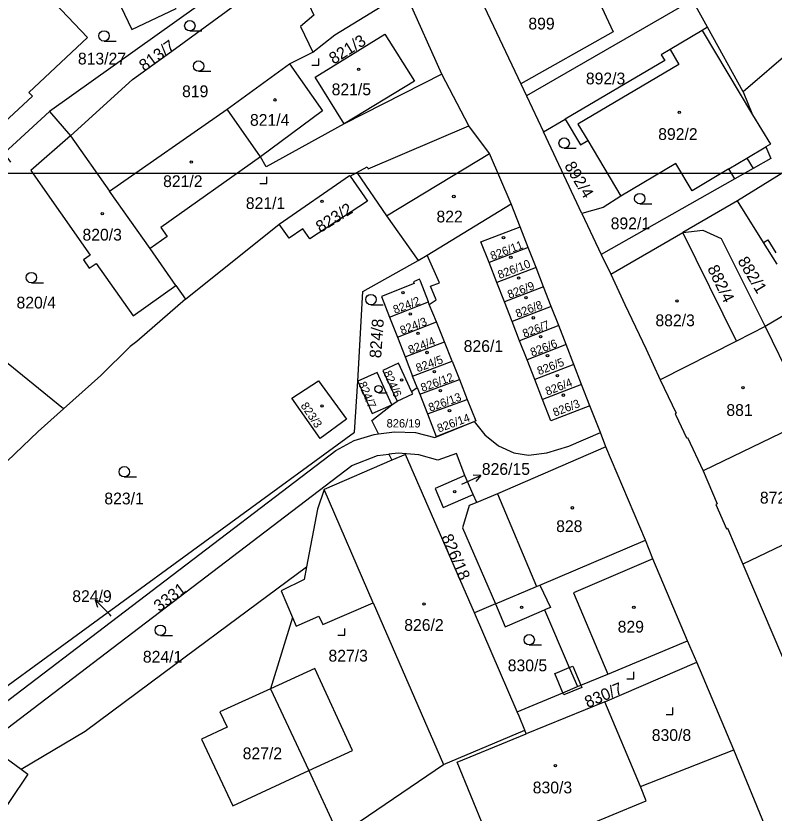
# Model space of a CAD drawing. Extents: x -496682 to -495776, y -1088797 to -1088018.
# Drawn here: x -496303.3 to -496193.9, y -1088256.7 to -1088141.5 of the extents above; entities that cross this region are included whole.
import ezdxf

# ---------------------------------------------------------------- set-up
doc = ezdxf.new("R2010")
doc.units = 0
for name, color, linetype in [('Hranice parcel', 7, 'Continuous'), ('Parcelní čísla', 7, 'Continuous'), ('Pop  PČ popisy', 7, 'Continuous'), ('Vnitřní kresba', 7, 'Continuous'), ('Vrstva 63', 7, 'Continuous'), ('Značky budov', 7, 'Continuous'), ('Značky kultur', 7, 'Continuous')]:
    doc.layers.add(name, color=color, linetype=linetype)

msp = doc.modelspace()

# ---------------------------------------------------------------- linework, layer by layer
at = {"layer": 'Hranice parcel'}
for p, q in [((-496241.8, -1088149.94), (-496247.14, -1088138.02)), ((-496205.62, -1088139.25), (-496229.59, -1088153.09)), ((-496203.46, -1088143.17), (-496205.62, -1088139.25)), ((-496198.32, -1088152.5), (-496203.46, -1088143.17)), ((-496187.08, -1088142.78), (-496198.32, -1088152.5)), ((-496263.79, -1088148.47), (-496260.45, -1088146.79)), ((-496272.8, -1088155.01), (-496263.79, -1088148.47)), ((-496237.95, -1088157.41), (-496241.8, -1088149.94)), ((-496229.59, -1088153.09), (-496227.14, -1088158.28)), ((-496298.45, -1088155.33), (-496295.42, -1088158.88)), ((-496289.8, -1088166.88), (-496272.8, -1088155.01)), ((-496268.02, -1088161.9), (-496272.8, -1088155.01)), ((-496227.14, -1088158.28), (-496224.02, -1088156.48)), ((-496295.42, -1088158.88), (-496289.8, -1088166.88)), ((-496221.59, -1088170.07), (-496227.14, -1088158.28)), ((-496255.04, -1088164.71), (-496254.07, -1088164.17)), ((-496199.54, -1088165.08), (-496218.8, -1088175.99)), ((-496283.92, -1088175.15), (-496289.8, -1088166.88)), ((-496199.12, -1088168.24), (-496207.04, -1088172.83)), ((-496243.96, -1088176.09), (-496231.8, -1088168.7)), ((-496230.52, -1088171.99), (-496231.8, -1088168.7)), ((-496221.59, -1088170.07), (-496218.8, -1088175.99)), ((-496278.83, -1088182.48), (-496265.29, -1088171.61)), ((-496229.35, -1088174.98), (-496230.52, -1088171.99)), ((-496217.42, -1088178.85), (-496207.04, -1088172.83)), ((-496199.29, -1088188.52), (-496207.04, -1088172.83)), ((-496280.24, -1088180.51), (-496283.92, -1088175.15)), ((-496229.35, -1088174.98), (-496234.99, -1088177.17)), ((-496228.23, -1088177.87), (-496229.35, -1088174.98)), ((-496245.26, -1088176.88), (-496243.96, -1088176.09)), ((-496218.8, -1088175.99), (-496217.42, -1088178.85)), ((-496233.87, -1088180.06), (-496234.99, -1088177.17)), ((-496228.23, -1088177.87), (-496233.87, -1088180.06)), ((-496227.14, -1088180.67), (-496228.23, -1088177.87)), ((-496296.45, -1088198.31), (-496318.2, -1088180.61)), ((-496280.24, -1088180.51), (-496278.83, -1088182.48)), ((-496232.78, -1088182.86), (-496233.87, -1088180.06)), ((-496227.14, -1088180.67), (-496232.78, -1088182.86)), ((-496226.03, -1088183.51), (-496227.14, -1088180.67)), ((-496249.36, -1088185.06), (-496243.73, -1088182.86)), ((-496243.63, -1088183.24), (-496243.73, -1088182.86)), ((-496242.58, -1088185.76), (-496243.63, -1088183.24)), ((-496231.67, -1088185.7), (-496232.78, -1088182.86)), ((-496226.03, -1088183.51), (-496231.67, -1088185.7)), ((-496224.95, -1088186.28), (-496226.03, -1088183.51)), ((-496190.77, -1088183.83), (-496195.13, -1088186.39)), ((-496249.36, -1088185.06), (-496248.24, -1088187.94)), ((-496248.24, -1088187.94), (-496242.58, -1088185.76)), ((-496241.45, -1088188.63), (-496242.58, -1088185.76)), ((-496230.59, -1088188.48), (-496231.67, -1088185.7)), ((-496224.95, -1088186.28), (-496230.59, -1088188.48)), ((-496223.88, -1088189.03), (-496224.95, -1088186.28)), ((-496195.13, -1088186.39), (-496199.29, -1088188.52)), ((-496248.24, -1088187.94), (-496247.13, -1088190.79)), ((-496247.13, -1088190.79), (-496241.45, -1088188.63)), ((-496240.33, -1088191.44), (-496241.45, -1088188.63)), ((-496229.52, -1088191.23), (-496230.59, -1088188.48)), ((-496223.88, -1088189.03), (-496229.52, -1088191.23)), ((-496222.77, -1088191.9), (-496223.88, -1088189.03)), ((-496199.29, -1088188.52), (-496210.3, -1088194.11)), ((-496247.13, -1088190.79), (-496246.04, -1088193.57)), ((-496246.04, -1088193.57), (-496240.33, -1088191.44)), ((-496240.33, -1088191.44), (-496239.28, -1088194.09)), ((-496228.41, -1088194.09), (-496229.52, -1088191.23)), ((-496222.77, -1088191.9), (-496228.41, -1088194.09)), ((-496221.65, -1088194.78), (-496222.77, -1088191.9)), ((-496245.4, -1088195.22), (-496246.04, -1088193.57)), ((-496245.02, -1088196.2), (-496239.28, -1088194.09)), ((-496239.28, -1088194.09), (-496238.15, -1088196.96)), ((-496227.29, -1088196.97), (-496228.41, -1088194.09)), ((-496221.65, -1088194.78), (-496227.29, -1088196.97)), ((-496220.45, -1088197.86), (-496221.65, -1088194.78)), ((-496246.18, -1088195.79), (-496245.4, -1088195.22)), ((-496245.4, -1088195.22), (-496245.02, -1088196.2)), ((-496249.06, -1088197.72), (-496248.29, -1088197.2)), ((-496245.02, -1088196.2), (-496243.91, -1088199.04)), ((-496243.91, -1088199.04), (-496238.15, -1088196.96)), ((-496218.94, -1088201.74), (-496220.45, -1088197.86)), ((-496218.13, -1088203.82), (-496218.94, -1088201.74)), ((-496212.43, -1088217.26), (-496218.13, -1088203.82)), ((-496249.48, -1088204.87), (-496249.04, -1088205.74)), ((-496237.31, -1088210.69), (-496238.5, -1088207.96)), ((-496236.79, -1088211.83), (-496237.31, -1088210.69)), ((-496198.35, -1088220.77), (-496191.24, -1088237.47)), ((-496234.09, -1088226.5), (-496237.12, -1088227.8)), ((-496230.93, -1088242.07), (-496237.12, -1088227.8)), ((-496263.4, -1088228.45), (-496266.56, -1088238.74)), ((-496205.03, -1088234.9), (-496206.35, -1088231.82)), ((-496218.27, -1088240.64), (-496205.03, -1088234.9)), ((-496199.66, -1088247.57), (-496205.03, -1088234.9)), ((-496218.27, -1088240.64), (-496229.63, -1088245.28)), ((-496213.15, -1088252.87), (-496218.27, -1088240.64)), ((-496302.57, -1088250.38), (-496293.33, -1088244.86)), ((-496241.58, -1088249.7), (-496229.85, -1088244.73)), ((-496229.63, -1088245.28), (-496229.85, -1088244.73)), ((-496307.55, -1088246.72), (-496302.57, -1088250.38)), ((-496213.15, -1088252.87), (-496199.66, -1088247.57)), ((-496188.02, -1088275.91), (-496199.66, -1088247.57)), ((-496261.03, -1088250.54), (-496256.69, -1088259.96))]:
    msp.add_line(p, q, dxfattribs=at)
for points in [[(-496284.92, -1088130.53), (-496291.31, -1088133.56), (-496286.59, -1088143.52), (-496280.17, -1088140.48), (-496284.92, -1088130.53)], [(-496265.89, -1088136.18), (-496267.72, -1088133.38), (-496298.45, -1088155.33)], [(-496262.1, -1088133.95), (-496260.32, -1088137.8), (-496261.74, -1088138.32), (-496260.3, -1088141.44), (-496262.22, -1088143.07), (-496260.45, -1088146.79)], [(-496295.42, -1088158.88), (-496286.46, -1088150.74), (-496280.26, -1088146.23), (-496271.7, -1088140.01), (-496265.89, -1088136.18)], [(-496316.44, -1088148.1), (-496316.33, -1088148), (-496315.31, -1088149.08), (-496325.51, -1088158.67), (-496317.28, -1088167.48), (-496305.43, -1088156.36), (-496304.95, -1088156.9), (-496300.93, -1088153.13), (-496301.44, -1088152.61), (-496292.98, -1088144.67), (-496299.6, -1088137.62)], [(-496260.45, -1088146.79), (-496257.27, -1088144.28), (-496247.14, -1088138.02)], [(-496236.14, -1088139.28), (-496230.41, -1088151.36), (-496229.59, -1088153.09)], [(-496203.46, -1088143.17), (-496204.25, -1088143.65), (-496208.86, -1088146.39), (-496210.14, -1088147.15), (-496209.63, -1088148), (-496224.02, -1088156.48)], [(-496250.04, -1088144.19), (-496245.79, -1088150.95), (-496255.91, -1088157.15), (-496260.09, -1088150.37), (-496250.04, -1088144.19)], [(-496263.79, -1088148.47), (-496259.06, -1088155.27), (-496268.02, -1088161.9)], [(-496241.8, -1088149.94), (-496255.91, -1088157.15), (-496267.18, -1088163.34), (-496268.02, -1088161.9)], [(-496198.32, -1088152.5), (-496196.96, -1088155.81), (-496194.39, -1088160.08), (-496195.03, -1088160.46), (-496194.34, -1088162.14), (-496196.89, -1088163.58), (-496199.54, -1088165.08)], [(-496304.04, -1088162.67), (-496305.02, -1088161.37), (-496298.45, -1088155.33)], [(-496224.02, -1088156.48), (-496221.81, -1088160.18), (-496220.77, -1088159.55), (-496215.96, -1088167.6)], [(-496254.07, -1088164.17), (-496252.59, -1088163.36), (-496252.44, -1088163.62), (-496237.95, -1088157.41)], [(-496231.8, -1088168.7), (-496234.94, -1088161.4), (-496237.95, -1088157.41)], [(-496182.92, -1088158.15), (-496186.17, -1088160.2), (-496199.12, -1088168.24)], [(-496295.42, -1088158.88), (-496301.16, -1088163.87), (-496292.58, -1088176.09), (-496293.56, -1088176.78), (-496292.71, -1088177.99), (-496291.73, -1088177.3), (-496286.4, -1088184.88), (-496280.24, -1088180.51)], [(-496268.02, -1088161.9), (-496282.4, -1088172.11), (-496281.47, -1088173.42), (-496283.92, -1088175.15)], [(-496199.54, -1088165.08), (-496200.38, -1088163.65), (-496205.67, -1088166.81), (-496208.04, -1088162.84), (-496215.96, -1088167.6)], [(-496265.29, -1088171.61), (-496255.13, -1088164.58), (-496255.04, -1088164.71)], [(-496255.04, -1088164.71), (-496252.56, -1088168.29), (-496260.9, -1088173.75), (-496261.91, -1088172.29), (-496263.88, -1088173.65), (-496265.29, -1088171.61)], [(-496254.07, -1088164.17), (-496249.82, -1088170.42), (-496245.26, -1088176.88)], [(-496215.96, -1088167.6), (-496218.53, -1088169.21), (-496221.59, -1088170.07)], [(-496193.41, -1088177.4), (-496195.37, -1088174.27), (-496199.12, -1088168.24)], [(-496234.99, -1088177.17), (-496236.17, -1088174.19), (-496230.52, -1088171.99)], [(-496207.04, -1088172.83), (-496204.16, -1088172.47), (-496201.5, -1088173.7), (-496195.13, -1088186.39)], [(-496243.63, -1088183.24), (-496242.63, -1088182.58), (-496243.44, -1088180.59), (-496242.16, -1088180.08), (-496243.96, -1088176.09)], [(-496253.97, -1088194.3), (-496253.21, -1088181.35), (-496245.26, -1088176.88)], [(-496217.42, -1088178.85), (-496215.39, -1088183.24), (-496212.35, -1088189.69), (-496210.3, -1088194.11)], [(-496243.73, -1088182.86), (-496244.92, -1088179.86), (-496245.04, -1088179.57), (-496245.9, -1088179.95), (-496245.8, -1088180.2), (-496250.53, -1088182.08), (-496249.36, -1088185.06)], [(-496278.83, -1088182.48), (-496285.87, -1088188.57), (-496286.81, -1088189.29), (-496291.03, -1088193.47), (-496296.45, -1088198.31)], [(-496246.18, -1088195.79), (-496248.08, -1088191.7), (-496250.36, -1088192.76), (-496248.29, -1088197.2)], [(-496249.06, -1088197.72), (-496251.15, -1088193.04), (-496253.97, -1088194.3)], [(-496311.81, -1088243.59), (-496254.42, -1088201.7), (-496253.97, -1088194.3)], [(-496263.48, -1088196.77), (-496259.62, -1088194.28), (-496255.59, -1088199.81)], [(-496253.97, -1088194.3), (-496251.88, -1088198.98), (-496249.06, -1088197.72)], [(-496210.3, -1088194.11), (-496208.02, -1088198.95), (-496208.16, -1088199.02), (-496208.06, -1088199.23), (-496206.51, -1088202.51), (-496206.37, -1088202.45), (-496204.1, -1088207.28)], [(-496248.29, -1088197.2), (-496246.02, -1088196.14), (-496246.18, -1088195.79)], [(-496255.59, -1088199.81), (-496259.41, -1088202.59), (-496263.48, -1088196.77)], [(-496238.15, -1088196.96), (-496236.93, -1088200.02), (-496237.18, -1088200.12)], [(-496220.45, -1088197.86), (-496226.09, -1088200.05), (-496227.29, -1088196.97)], [(-496330.37, -1088232.05), (-496329.58, -1088231.08), (-496327.35, -1088228.88), (-496319.53, -1088220.58), (-496313.61, -1088214.48), (-496300.1, -1088201.57), (-496296.45, -1088198.31)], [(-496250.98, -1088201.92), (-496251.95, -1088200), (-496249.06, -1088197.72)], [(-496185.54, -1088197.33), (-496188.66, -1088199.81), (-496204.1, -1088207.28)], [(-496243.91, -1088199.04), (-496242.64, -1088202.29), (-496237.18, -1088200.12)], [(-496250.98, -1088201.92), (-496248.64, -1088201.63), (-496245.64, -1088201.74), (-496242.85, -1088202.47), (-496237.18, -1088200.12)], [(-496237.18, -1088200.12), (-496235.63, -1088202.06), (-496233.62, -1088203.63), (-496231.44, -1088204.65), (-496229.32, -1088205), (-496226.65, -1088204.68), (-496223.49, -1088203.7), (-496218.94, -1088201.74)], [(-496310.18, -1088244.79), (-496257.12, -1088204.31), (-496254.49, -1088202.87), (-496251.61, -1088202), (-496250.98, -1088201.92)], [(-496218.13, -1088203.82), (-496233.8, -1088210.57), (-496236.79, -1088211.83)], [(-496307.55, -1088246.72), (-496254.8, -1088206.49), (-496251.12, -1088205.07), (-496249.48, -1088204.87)], [(-496238.5, -1088207.96), (-496239.73, -1088204.77), (-496242.39, -1088205.73), (-496245.16, -1088204.93), (-496248.13, -1088204.71), (-496249.48, -1088204.87)], [(-496237.12, -1088227.8), (-496247.06, -1088204.88), (-496249.04, -1088205.74)], [(-496249.04, -1088205.74), (-496258.79, -1088209.96), (-496259.78, -1088212.78), (-496261.37, -1088221.14)], [(-496204.1, -1088207.28), (-496202.07, -1088212.04), (-496202.25, -1088212.12), (-496200.73, -1088215.63), (-496200.57, -1088215.56), (-496198.35, -1088220.77)], [(-496238.5, -1088207.96), (-496242.81, -1088209.83), (-496241.65, -1088212.57), (-496237.31, -1088210.69)], [(-496236.79, -1088211.83), (-496237.87, -1088212.28), (-496238.84, -1088215.51), (-496234.09, -1088226.5)], [(-496179.86, -1088211.45), (-496182.82, -1088213.25), (-496186.02, -1088214.8), (-496198.35, -1088220.77)], [(-496234.09, -1088226.5), (-496228.16, -1088223.97), (-496227.66, -1088223.76), (-496212.43, -1088217.26)], [(-496206.35, -1088231.82), (-496211.35, -1088219.97), (-496212.43, -1088217.26)], [(-496293.33, -1088244.86), (-496282.06, -1088236.51), (-496272.7, -1088229.58), (-496261.37, -1088221.14)], [(-496261.37, -1088221.14), (-496261.72, -1088222.97), (-496265.04, -1088224.59), (-496263.4, -1088228.45)], [(-496263.4, -1088228.45), (-496262.87, -1088229.7), (-496259.56, -1088228.24), (-496259, -1088229.48), (-496251.75, -1088226.32), (-496241.58, -1088249.7)], [(-496234.09, -1088226.5), (-496232.66, -1088229.8), (-496228.12, -1088227.84), (-496227, -1088227.36), (-496223.42, -1088235.69), (-496222.24, -1088238.44)], [(-496222.24, -1088238.44), (-496221.74, -1088238.24), (-496217.87, -1088236.62), (-496206.35, -1088231.82)], [(-496261.03, -1088250.54), (-496254.74, -1088247.66), (-496260.18, -1088235.84), (-496266.56, -1088238.74)], [(-496266.56, -1088238.74), (-496273.85, -1088242.06), (-496272.81, -1088244.31), (-496276.5, -1088246.03), (-496272.01, -1088255.68), (-496261.03, -1088250.54)], [(-496230.93, -1088242.07), (-496224.34, -1088239.32), (-496222.24, -1088238.44)], [(-496229.85, -1088244.73), (-496230.66, -1088242.69), (-496230.93, -1088242.07)], [(-496233.69, -1088263.8), (-496239.59, -1088249.36), (-496229.63, -1088245.28)], [(-496256.69, -1088259.96), (-496256.02, -1088259.51), (-496241.58, -1088249.7)], [(-496302.57, -1088250.38), (-496301.59, -1088251.1), (-496306.94, -1088258.98)], [(-496233.69, -1088263.8), (-496212.34, -1088254.94), (-496213.15, -1088252.87)]]:
    msp.add_lwpolyline(points, dxfattribs=at)
at = {"layer": 'Pop  PČ popisy'}
for p, q in [((-496238.92, -1088209.2), (-496236.2, -1088207.93)), ((-496236.2, -1088207.93), (-496237.32, -1088207.9)), ((-496236.2, -1088207.93), (-496236.9, -1088208.81)), ((-496289.77, -1088228.03), (-496291.89, -1088225.91)), ((-496291.89, -1088225.91), (-496290.83, -1088226.26)), ((-496291.89, -1088225.91), (-496291.54, -1088226.97)), ((-496289.57, -1088228.24), (-496289.77, -1088228.03))]:
    msp.add_line(p, q, dxfattribs=at)
at = {"layer": 'Vnitřní kresba'}
for p, q in [((-496222.8, -1088131.48), (-496217.11, -1088143.84)), ((-496217.11, -1088143.84), (-496230.41, -1088151.36)), ((-496204.25, -1088143.65), (-496196.96, -1088155.81)), ((-496208.86, -1088146.39), (-496207.59, -1088148.55)), ((-496207.59, -1088148.55), (-496222.17, -1088157.19)), ((-496222.17, -1088157.19), (-496220.77, -1088159.55)), ((-496197.78, -1088162.1), (-496195.03, -1088160.46)), ((-496249.82, -1088170.42), (-496234.94, -1088161.4)), ((-496200.38, -1088163.65), (-496197.78, -1088162.1)), ((-496197.78, -1088162.1), (-496196.89, -1088163.58)), ((-496195.37, -1088174.27), (-496194.78, -1088173.9)), ((-496194.78, -1088173.9), (-496193.61, -1088175.79)), ((-496195.13, -1088186.39), (-496188.66, -1088199.81)), ((-496251.75, -1088226.32), (-496258.79, -1088209.96)), ((-496233.8, -1088210.57), (-496228.16, -1088223.97)), ((-496211.35, -1088219.97), (-496222.82, -1088224.87)), ((-496227.66, -1088223.76), (-496226.14, -1088226.99)), ((-496222.82, -1088224.87), (-496217.87, -1088236.62)), ((-496226.14, -1088226.99), (-496227, -1088227.36)), ((-496225.49, -1088236.52), (-496225.15, -1088236.38)), ((-496225.15, -1088236.38), (-496223.42, -1088235.69)), ((-496223.42, -1088235.69), (-496222.89, -1088235.48)), ((-496222.89, -1088235.48), (-496221.74, -1088238.24)), ((-496224.34, -1088239.32), (-496225.49, -1088236.52)), ((-496266.56, -1088238.74), (-496261.03, -1088250.54)), ((-496221.6, -1088238.57), (-496224.21, -1088239.64)), ((-496221.74, -1088238.24), (-496221.6, -1088238.57)), ((-496224.21, -1088239.64), (-496224.34, -1088239.32))]:
    msp.add_line(p, q, dxfattribs=at)
at = {"layer": 'Vrstva 63'}
msp.add_lwpolyline([(-496137.35, -1088164.24), (-496137.35, -1088461.24), (-496557.35, -1088461.24), (-496557.35, -1088164.24)], close=True, dxfattribs=at)
at = {"layer": 'Značky budov'}
for centre in [(-496253.83, -1088149.25), (-496265.91, -1088153.67), (-496207.55, -1088155.47), (-496278, -1088162.65), (-496259.11, -1088168.33), (-496240.09, -1088167.63), (-496290.84, -1088170.11), (-496232.92, -1088173.59), (-496231.86, -1088176.41), (-496230.74, -1088179.41), (-496247.44, -1088181.54), (-496229.68, -1088182.23), (-496207.89, -1088182.71), (-496246.38, -1088184.59), (-496228.62, -1088185.16), (-496245.26, -1088187.41), (-496227.57, -1088187.87), (-496243.95, -1088190.17), (-496226.57, -1088190.63), (-496242.9, -1088192.93), (-496225.14, -1088193.51), (-496247.63, -1088194.14), (-496242.03, -1088195.69), (-496224.27, -1088196.33), (-496198.35, -1088195.25), (-496259.11, -1088197.88), (-496240.72, -1088198.57), (-496239.96, -1088210.28), (-496222.97, -1088212.61), (-496244.39, -1088226.5), (-496230.3, -1088226.97), (-496214.11, -1088227), (-496225.43, -1088249.85)]:
    msp.add_circle(centre, 0.175, dxfattribs=at)
at = {"layer": 'Značky kultur'}
for p, q in [((-496278.2, -1088143.71), (-496276.45, -1088143.71)), ((-496290.59, -1088145.18), (-496288.84, -1088145.18)), ((-496259.58, -1088148.67), (-496259.58, -1088147.67)), ((-496260.58, -1088148.67), (-496259.58, -1088148.67)), ((-496276.94, -1088149.53), (-496275.19, -1088149.53)), ((-496224.16, -1088160.66), (-496222.41, -1088160.66)), ((-496267.11, -1088165.77), (-496267.11, -1088164.77)), ((-496268.11, -1088165.77), (-496267.11, -1088165.77)), ((-496213.26, -1088168.69), (-496211.51, -1088168.69)), ((-496301.08, -1088180.1), (-496299.33, -1088180.1)), ((-496252.05, -1088183.27), (-496250.3, -1088183.27)), ((-496250.96, -1088195.98), (-496249.73, -1088195.98)), ((-496287.66, -1088208.15), (-496285.91, -1088208.15)), ((-496255.82, -1088231.02), (-496255.82, -1088230.02)), ((-496282.46, -1088231.05), (-496280.71, -1088231.05)), ((-496256.82, -1088231.02), (-496255.82, -1088231.02)), ((-496229.21, -1088232.41), (-496227.46, -1088232.41)), ((-496214.11, -1088237.3), (-496214.11, -1088236.3)), ((-496215.11, -1088237.3), (-496214.11, -1088237.3)), ((-496208.46, -1088242.47), (-496208.46, -1088241.47)), ((-496209.46, -1088242.47), (-496208.46, -1088242.47))]:
    msp.add_line(p, q, dxfattribs=at)
for centre, radius in [((-496278.2, -1088142.96), 0.75), ((-496290.59, -1088144.43), 0.75), ((-496276.94, -1088148.78), 0.75), ((-496224.16, -1088159.91), 0.75), ((-496213.26, -1088167.94), 0.75), ((-496301.08, -1088179.35), 0.75), ((-496252.05, -1088182.52), 0.75), ((-496250.96, -1088195.45), 0.525), ((-496287.66, -1088207.4), 0.75), ((-496282.46, -1088230.3), 0.75), ((-496229.21, -1088231.66), 0.75)]:
    msp.add_circle(centre, radius, dxfattribs=at)

# ---------------------------------------------------------------- texts
at = {"layer": 'Parcelní čísla'}
for s, height, p in [('899', 1.7, (-496229.33, -1088143.5)), ('813/27', 1.7, (-496294.36, -1088148.56)), ('892/3', 1.7, (-496221.03, -1088151.43)), ('821/5', 1.7, (-496257.73, -1088153)), ('819', 1.7, (-496279.32, -1088153.28)), ('821/4', 1.7, (-496269.52, -1088157.42)), ('892/2', 1.7, (-496210.59, -1088159.46)), ('821/2', 1.7, (-496282.06, -1088166.27)), ('821/1', 1.7, (-496270.12, -1088169.44)), ('822', 1.7, (-496242.6, -1088171.38)), ('892/1', 1.7, (-496217.45, -1088172.36)), ('820/3', 1.7, (-496293.7, -1088174)), ('820/4', 1.7, (-496303.22, -1088183.81)), ('882/3', 1.7, (-496210.99, -1088186.37)), ('826/1', 1.7, (-496238.67, -1088190.09)), ('881', 1.7, (-496200.75, -1088199.33)), ('826/19', 1.2, (-496249.8, -1088201)), ('826/15', 1.7, (-496236.05, -1088207.85)), ('823/1', 1.7, (-496290.54, -1088212.11)), ('872', 1.7, (-496195.91, -1088211.99)), ('828', 1.7, (-496225.32, -1088216.11)), ('824/9', 1.7, (-496295.17, -1088226.22)), ('826/2', 1.7, (-496247.25, -1088230.38)), ('829', 1.7, (-496216.44, -1088230.63)), ('824/1', 1.7, (-496284.98, -1088234.97)), ('827/3', 1.7, (-496258.19, -1088234.82)), ('830/5', 1.7, (-496232.31, -1088236.22)), ('830/8', 1.7, (-496211.52, -1088246.29)), ('827/2', 1.7, (-496270.57, -1088248.93)), ('830/3', 1.7, (-496228.7, -1088253.86))]:
    msp.add_text(s, height=height, dxfattribs=at).set_placement(p)
for s, height, rotation, p in [('821/3', 1.7, 32, (-496257.44, -1088148.59)), ('813/7', 1.7, 36, (-496284.76, -1088149.61)), ('892/4', 1.7, 301, (-496224.19, -1088163.19)), ('823/2', 1.7, 32, (-496259.35, -1088172.91)), ('826/11', 1.2, 21, (-496234.55, -1088176.84)), ('882/1', 1.7, 301, (-496199.19, -1088176.94)), ('826/10', 1.2, 21, (-496233.49, -1088179.56)), ('882/4', 1.7, 296, (-496203.54, -1088178.02)), ('826/9', 1.2, 21, (-496232.08, -1088182.41)), ('824/2', 1.2, 21, (-496248.59, -1088184.6)), ('826/8', 1.2, 21, (-496230.91, -1088185.18)), ('824/8', 1.7, 86, (-496250.59, -1088191.03)), ('824/3', 1.2, 21, (-496247.59, -1088187.59)), ('826/7', 1.2, 21, (-496229.9, -1088188.05)), ('824/4', 1.2, 21, (-496246.41, -1088190.41)), ('826/6', 1.2, 21, (-496228.78, -1088190.76)), ('824/5', 1.2, 20, (-496245.31, -1088193.03)), ('826/5', 1.2, 21, (-496227.79, -1088193.46)), ('824/6', 1.2, 294, (-496250.3, -1088193.09)), ('826/12', 1.2, 20, (-496244.62, -1088195.87)), ('824/7', 1.2, 293, (-496253.92, -1088194.67)), ('826/4', 1.2, 21, (-496226.61, -1088196.4)), ('826/13', 1.2, 20, (-496243.5, -1088198.74)), ('826/3', 1.2, 21, (-496225.52, -1088199.44)), ('823/3', 1.2, 304, (-496262.26, -1088197.86)), ('826/14', 1.2, 20, (-496242.25, -1088201.74)), ('826/18', 1.7, 293, (-496241.94, -1088216.82)), ('3331', 1.7, 37, (-496282.61, -1088227.7)), ('830/7', 1.7, 23, (-496220.77, -1088241.54))]:
    msp.add_text(s, height=height, rotation=rotation, dxfattribs=at).set_placement(p)

doc.saveas('drawing.dxf')
